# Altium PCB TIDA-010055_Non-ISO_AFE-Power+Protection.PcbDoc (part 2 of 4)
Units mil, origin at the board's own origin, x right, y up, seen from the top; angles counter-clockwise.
Board outline 3622.05 x 4330.71 mil, 4 copper layers (Top Layer, GND Layer, PWR Layer, Bottom Layer), stack 63.6 mil thick; 398 components, 177 nets, 1104 pads, 428 vias.
Unrouted connection lines stored in the file: 1.
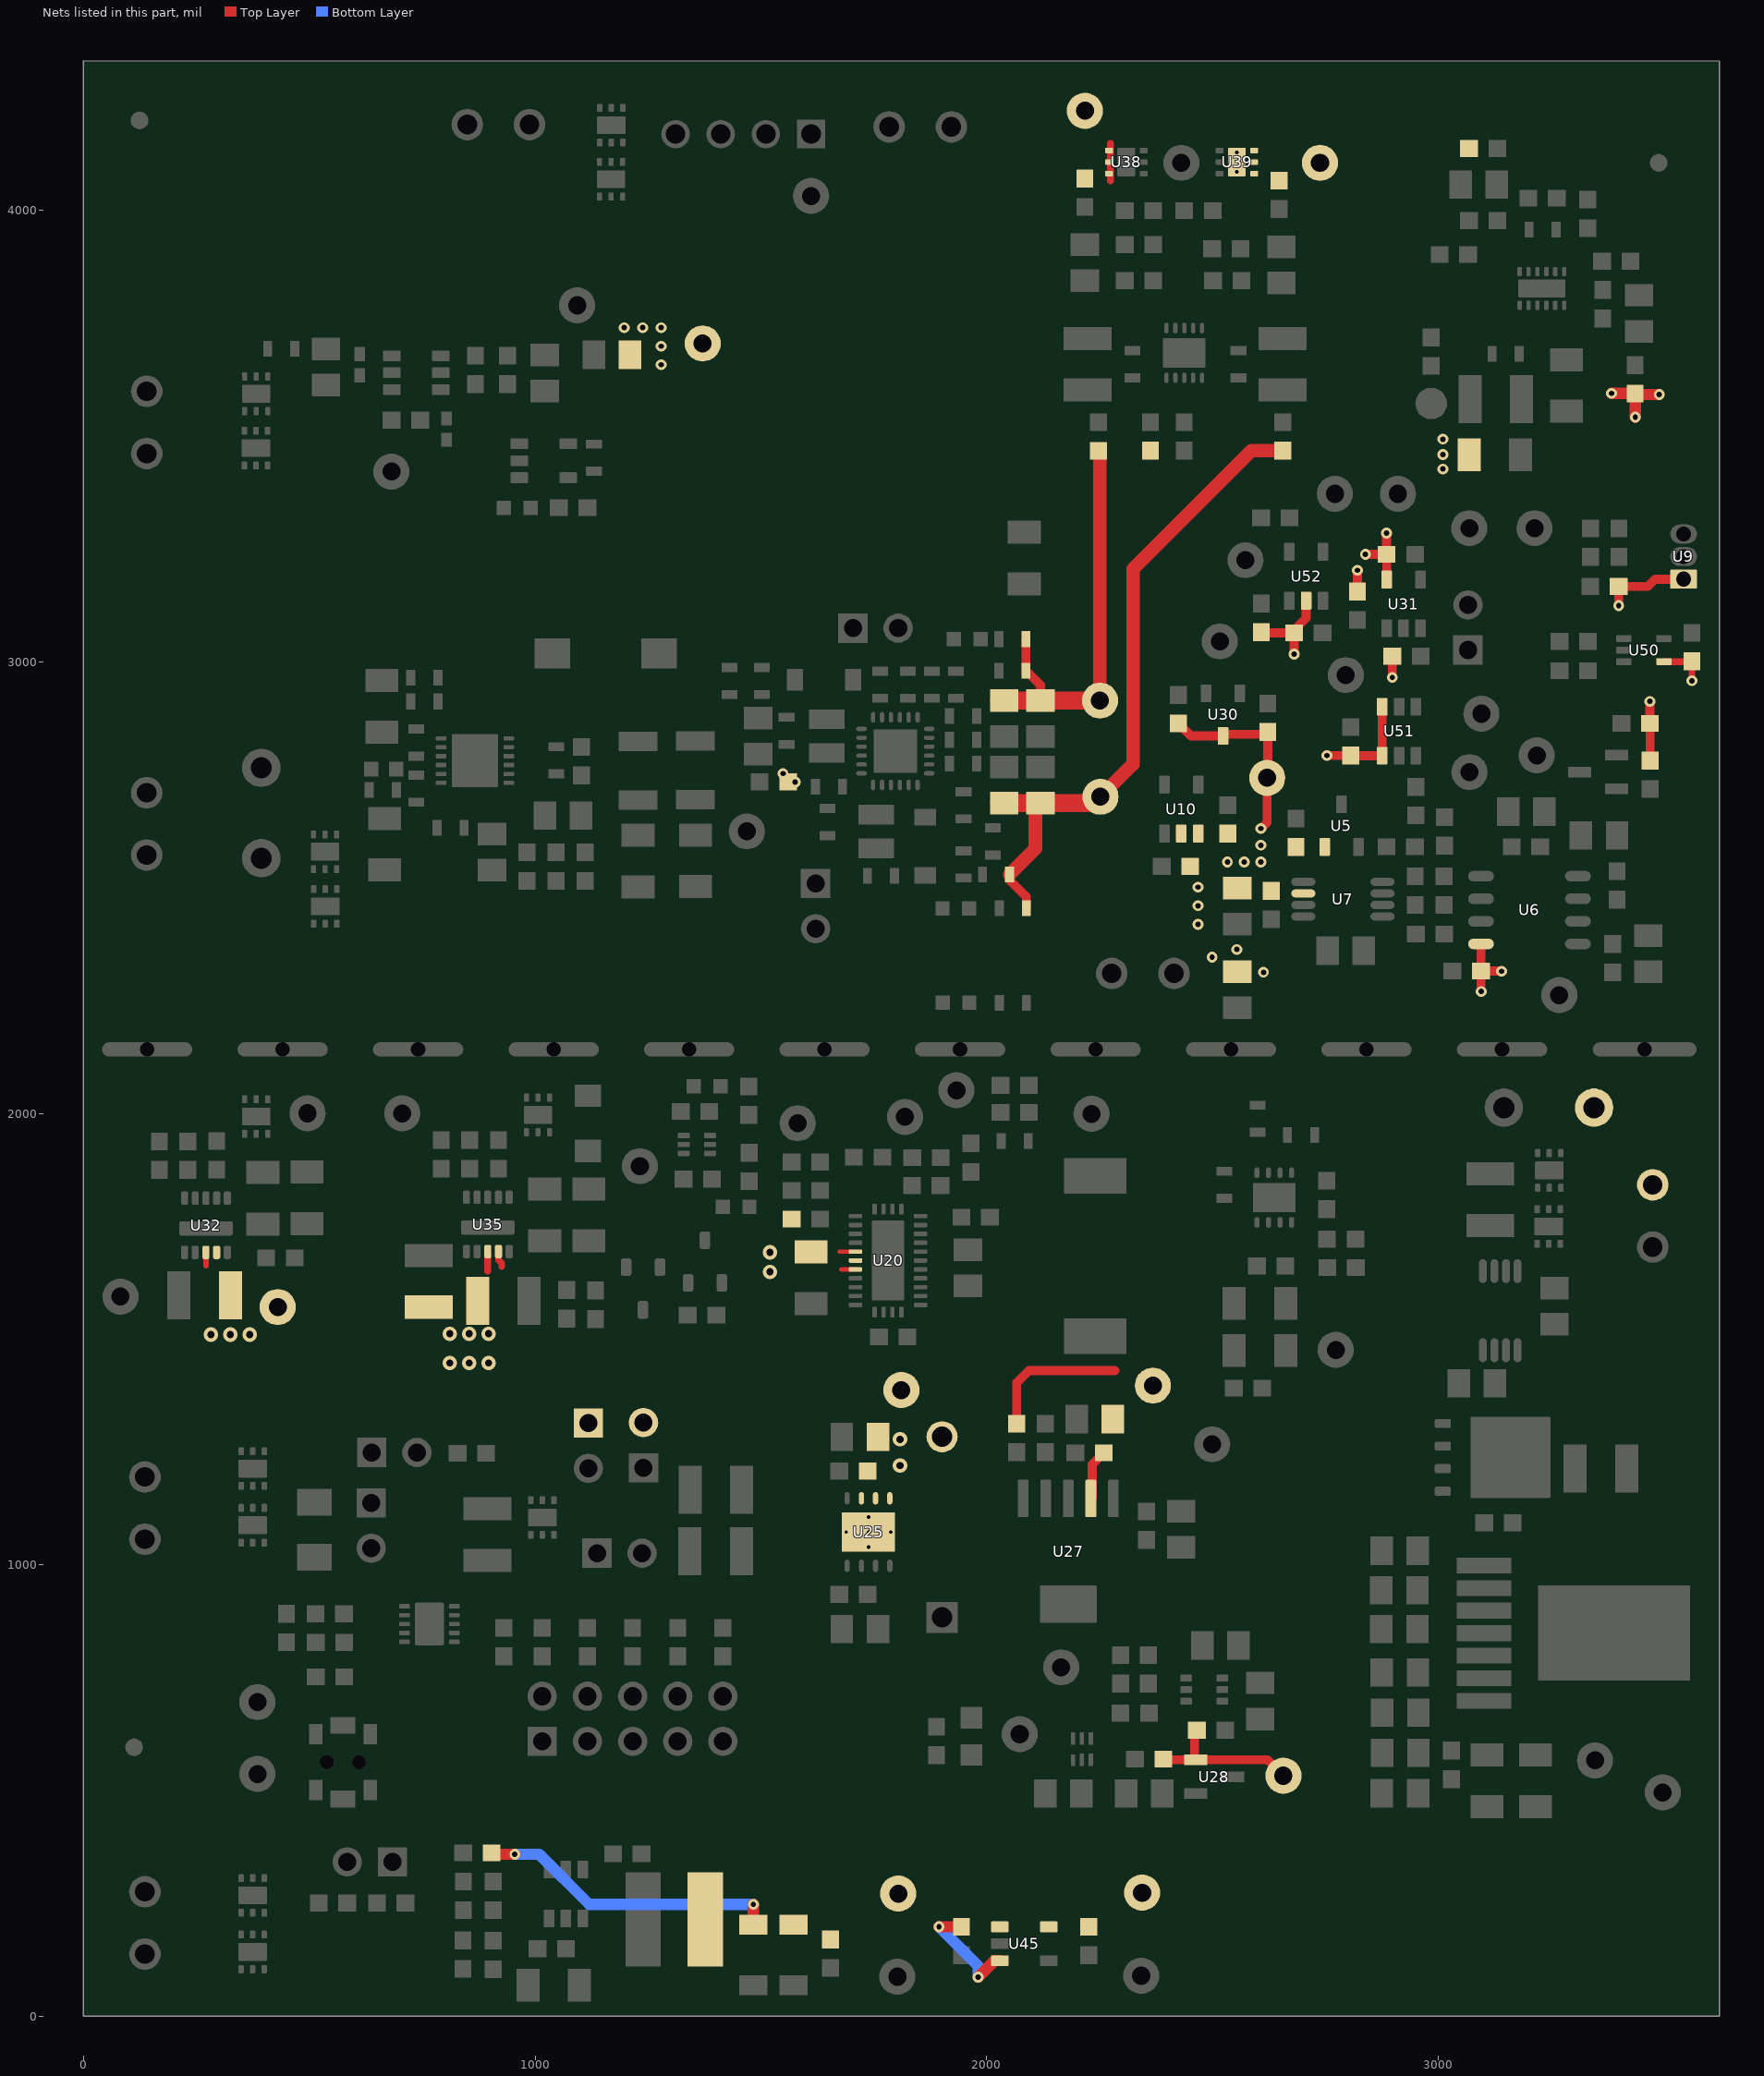
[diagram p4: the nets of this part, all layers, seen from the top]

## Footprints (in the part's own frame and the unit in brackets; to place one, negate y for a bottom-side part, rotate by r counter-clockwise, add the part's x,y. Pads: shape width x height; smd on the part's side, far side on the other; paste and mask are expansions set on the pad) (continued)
SW_PTS820 [mm] "SMT, 2-Leads, Body 3.9x2.9mm"
  rect 0.95x1.4 smd: 1(-2.075,0) 2(2.075,0)
  round 0.8 hole 0.8 unplated: MH1(0,0.9) MH2(0,-0.9)
  rect 1.15x0.75 smd: MP1(-1.575,1.525) MP2(1.575,1.525) MP3(1.575,-1.525) MP4(-1.575,-1.525)
  silkscreen extent -2.45,-2.2 2.45,2.2, body extent -2.25,-1.45 2.25,1.45, height 2
WE-PD-S [mm]
  rect 2x1.7 smd: 1(-3,0) 2(3,0)
  silkscreen extent -4.3,-4 4.3,4, body extent -3.8,-3.82 3.8,3.77, height 3.5
WE-PD_1050 [mm] "WERTH"
  rect 2x3.5 smd: 1(-4.5,0) 2(4.5,0)
  silkscreen extent -5,-5 5,5, body extent -5,-5 5,5, height 4.75
WE-SPC_4838 [mm] "WURTH"
  rect 2x5.3 smd: 1(-1.75,0) 2(1.75,0)
  silkscreen extent -0.48,-2.65 0.48,2.65, body extent -2.55,-2.55 2.55,2.55, height 4.1
WE_LQS_252012 [mm] "SMD, 2-Leads, Body 2.5x2mm, Pitch 1.9mm"
  rect 1.1x2 smd: 1(-0.95,0) 2(0.95,0)
  silkscreen extent -0.1,-1 0.1,1, body extent -1.25,-1 1.25,1, height 1.2
WEEE_Minimum [mil] "WEEElie bin"
  silkscreen extent -95,-172 99,104
Wurth_61300411021 [mm] "Header, 2.54 mm, 4x1, R/A, TH"
  rect 1.6x1.6 hole 1.1: 1(-3.81,0)
  round 1.6 hole 1.1: 2(-1.27,0) 3(1.27,0) 4(3.81,0)
  silkscreen extent -5.5,-4.04 5.08,-1.5, body extent -5.08,-10.04 5.08,0.32, height 2.55

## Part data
C1: "CAP, CERM, 4700 pF, 100 V, +/- 10%, X7R, 0603", Cap_Case=0603, Manufacturer=AVX, Supplier Part Number 1=478-1203-1-ND, TempCo=X7R, Tolerance_%=10, Value1="0.136 ohm", Value2=100V, ValueDisplayed=4700pF
C2: library part C0603C103J5RACTU, "CAP, CERM, 0.01 µF, 50 V, +/- 5%, X7R, 0603", Cap_Case=0603, Manufacturer="TDK Corporation", Supplier Part Number 1=445-5662-1-ND, TempCo=X7R, Tolerance_%=5, Value1=Unknown, Value2=50V, ValueDisplayed=0.01µF
C3 C4 C123: "CAP, CERM, 2.2 µF, 50 V,+/- 10%, X7R, 1206", Cap_Case=1206, Manufacturer="Taiyo Yuden", Supplier Part Number 1=587-2911-1-ND, TempCo=X7R, Tolerance_%=10, Value2=50V, ValueDisplayed=2.2µF
C5 C19 C23 C28 C29 C84: library part C1608X7R1H104K, "CAP, CERM, 0.12µF ±10% 50V Ceramic Capacitor X7R 0603", Cap_Case=0603, Manufacturer=KEMET, Supplier Part Number 1=399-13273-1-ND, TempCo=X7R, Tolerance_%=10, Value1="0.017 ohm", Value2=50V, ValueDisplayed=0.1µF
C6 C7: "CAP, CERM, 100 µF, 10 V, +/- 20%, X5R, 1210", Cap_Case=1210, Manufacturer=KEMET, Supplier Part Number 1=399-11631-1-ND, TempCo=X5R, Tolerance_%=20, Value1=Unknown, Value2=10V, ValueDisplayed=100µF
C8 C11: "CAP, CERM, 0.1 µF, 100 V, +/- 10%, X7R, 0805", Cap_Case=0805, Manufacturer=Kemet, Supplier Part Number 1=399-3486-1-ND, TempCo=X7R, Tolerance_%=10, Value1="0.064 ohm", Value2=100V, ValueDisplayed=0.1µF
C9 C32 C43: library part GMK325AB7106MM-T, "CAP, CERM, 10µF ±10% 35V Ceramic Capacitor X7R 1210", Cap_Case=1210, Manufacturer="Taiyo Yuden", PartNumber=GMJ325KB7106KMHP, Supplier Part Number 1=587-4890-1-ND, TempCo=X7R, Tolerance_%=20, Value1=Unknown, Value2=35V, ValueDisplayed=10µF
C10: "CAP, CERM, 1000 pF, 16 V, +/- 10%, X7R, 0603", Cap_Case=0603, Manufacturer="Wurth Elektronik", Supplier Part Number 1=732-7953-1-ND, TempCo=X7R, Tolerance_%=10, Value1=Unknown, Value2=16V, ValueDisplayed=1000pF
C16 C17 C25 C26: "CAP, CERM, 10 µF, 25 V, +/- 10%, X7S, 0805", Cap_Case=0805, Manufacturer=MuRata, Supplier Part Number 1=490-10496-1-ND, TempCo=X7S, Tolerance_%=10, Value1=Unknown, Value2=25V, ValueDisplayed=10µF
C18 C27 C33 C35 C38 C44 C63 C64 C71 C98: library part GRM188R71E105KA12D, "CAP, CERM, 1 µF, 25 V, +/- 10%, X7R, 0603", Cap_Case=0603, Manufacturer="TDK Corporation", Supplier Part Number 1=445-6931-1-ND, TempCo=X7R, Tolerance_%=10, Value1=Unknown, Value2=25V, ValueDisplayed=1µF
C20: "CAP, CERM, 6.8 pF, 50 V, +/- 4%, C0G/NP0, 0603", Cap_Case=0603, Manufacturer=AVX, Supplier Part Number 1=478-1161-1-ND, TempCo=C0G/NP0, Tolerance_%=4, Value1="0.505 ohm", Value2=50V, ValueDisplayed=6.8pF
C21: library part GRM188R71C224KA01D, "CAP, CERM, 0.22 µF, 16 V, +/- 10%, X7R, 0603", Cap_Case=0603, Manufacturer="Taiyo Yuden", Supplier Part Number 1=587-1249-1-ND, TempCo=X7R, Tolerance_%=10, Value1=Unknown, Value2=16V, ValueDisplayed=0.22µF
C22: "CAP, CERM, 10 µF, 25 V,+/- 10%, X7S, 0805", Cap_Case=0805, Manufacturer=MuRata, Supplier Part Number 1=490-10496-1-ND, TempCo=X7S, Tolerance_%=10, Value2=25V, ValueDisplayed=10µF
C24: library part 06035A5R6CAT2A, "CAP, CERM, 5.6 pF, 50 V, +/- 5%, C0G/NP0, 0603", Cap_Case=0603, Manufacturer=KEMET, Supplier Part Number 1=399-9112-1-ND, TempCo=C0G/NP0, Tolerance_%=5, Value1="0.568 ohm", Value2=50V, ValueDisplayed=5.6pF
C30: "CAP, CERM, 4700 pF, 50 V, +/- 10%, X7R, 0603", Cap_Case=0603, Manufacturer="Wurth Elektronik", Supplier Part Number 1=732-8005-1-ND, TempCo=X7R, Tolerance_%=10, Value1=Unknown, Value2=50V, ValueDisplayed=4700pF
C31: "CAP, CERM, 0.01 µF, 16 V, +/- 10%, X7R, 0603", Cap_Case=0603, Manufacturer="Wurth Elektronik", Supplier Part Number 1=732-7959-1-ND, TempCo=X7R, Tolerance_%=10, Value1=Unknown, Value2=16V, ValueDisplayed=0.01µF
C34 C37 C39 C41: "CAP, CERM, 2.2uF, 10V, +/-10%, X7R, 0805", Cap_Case=0805, Manufacturer=Kemet, Supplier Part Number 1=399-3522-1-ND, TempCo=X7R, Tolerance_%=10, Value1="0.008 ohm", Value2=10V, ValueDisplayed=2.2µF
C36 C40 C42: "CAP, CERM, 0.01 µF, 16 V,+/- 10%, X7R, 0603", Cap_Case=0603, Manufacturer="Wurth Elektronik", Supplier Part Number 1=732-7959-1-ND, TempCo=X7R, Tolerance_%=10, Value2=16V, ValueDisplayed=0.01µF
C45: library part C3216X7R1E475M, "CAP, CERM, 4.7 µF, 25 V, +/- 20%, X7R, 1206", Cap_Case=1206, Manufacturer=TDK, Supplier Part Number 1=445-1424-1-ND, TempCo=X7R, Tolerance_%=20, Value1="0.0063 ohm", Value2=25V, ValueDisplayed=4.7µF
C46 C47 C49 C54 C56 C57 C58 C61 C99 C100 C119 C135 C136 C137 C138 C139: "CAP, CERM, 0.1 µF, 25 V,+/- 10%, X5R, 0603", Cap_Case=0603, Manufacturer=AVX, Supplier Part Number 1=478-1244-1-ND, TempCo=X5R, Tolerance_%=10, Value1="0.048 ohm", Value2=25V, ValueDisplayed=0.1µF
C48 C53: library part C0805C105K8RACTU, "CAP, CERM, 1uF, 10V, +/-10%, X7R, 0805", Cap_Case=0805, Manufacturer="Samsung Electro-Mechanics", Supplier Part Number 1=1276-1275-1-ND, TempCo=X7R, Tolerance_%=10, Value1="0.015 ohm", Value2=10V, ValueDisplayed=1µF
C50 C51 C52: library part GRM21BR71H105KA12L, "CAP, CERM, 1 µF, 50 V, +/- 10%, X7R, 0805", Cap_Case=0805, Manufacturer=MuRata, Supplier Part Number 1=445-8890-1-ND, TempCo=X7R, Tolerance_%=10, Value1=Unknown, Value2=50V, ValueDisplayed=1µF
C55: "CAP, CERM, 10uF, 16V, +/-20%, X5R, 0603", Cap_Case=0603, Manufacturer="Taiyo Yuden", Supplier Part Number 1=587-3238-1-ND, TempCo=X5R, Tolerance_%=20, Value1=Unknown, Value2=16V, ValueDisplayed=10µF
C59: library part CL10B105KQ8NNNC, "CAP, CERM, 1 µF, 6.3 V, +/- 10%, X7R, 0603", Cap_Case=0603, Manufacturer="TDK Corporation", Supplier Part Number 1=445-13246-1-ND, TempCo=X7R, Tolerance_%=10, Value1=Unknown, Value2=6.3V, ValueDisplayed=1µF
C60 C87 C88 C94 C95 C121: library part GRM21BR61E106KA73L, "CAP, CERM, 10 µF, 25 V, +/- 10%, X5R, 0805", Cap_Case=0805, Manufacturer="TDK Corporation", Supplier Part Number 1=445-14387-1-ND, TempCo=X5R, Tolerance_%=10, Value1=Unknown, Value2=25V, ValueDisplayed=10µF
C65: library part GRM31CR72A105KA01L, "CAP, CERM, 1 µF, 100 V, +/- 10%, X7R, 1206", Cap_Case=2220, Manufacturer="TDK Corporation", Supplier Part Number 1=445-4467-1-ND, TempCo=X7R, Tolerance_%=10, Value1=Unknown, Value2=100V, ValueDisplayed=1µF
C66: library part GRM32ER72A225KA35L, "CAP, CERM, 2.2 µF, 100 V, +/- 10%, X7R, 1210", Cap_Case=1210, Manufacturer="TDK Corporation", Supplier Part Number 1=445-4497-1-ND, TempCo=X7R, Tolerance_%=10, Value1="0.007 ohm", Value2=100V, ValueDisplayed=2.2µF
C67: library part GRM188R71C223KA01D, "CAP, CERM, 0.022 µF, 16 V,+/- 10%, X7R, 0603", Cap_Case=0603, Manufacturer=KEMET, Supplier Part Number 1=399-1093-1-ND, TempCo=X7R, Tolerance_%=10, Value2=16V, ValueDisplayed=0.022µF
C68 C69 C78 C101 C104 C105 C133: library part GRM32ER71J106KA12L, "CAP, CERM, 10µF ±20% 50V Ceramic Capacitor X7R 1210", Cap_Case=1210, Manufacturer="Taiyo Yuden", Supplier Part Number 1=445-4537-1-ND, TempCo=X7R, Tolerance_%=10, Value1=Unknown, Value2=63V, ValueDisplayed=10µF
C70 C124 C127 C131: library part GRM188R71H104KA93D, "CAP, CERM, 0.12µF ±10% 50V Ceramic Capacitor X7R 0603", Cap_Case=0603, Manufacturer=KEMET, Supplier Part Number 1=399-13273-1-ND, TempCo=X7R, Tolerance_%=10, Value2=50V, ValueDisplayed=0.1µF
C72 C76: "CAP, CERM, 10 µF, 16 V,+/- 20%, X5R, 0603", Cap_Case=0603, Manufacturer="Taiyo Yuden", Supplier Part Number 1=587-3238-1-ND, TempCo=X5R, Tolerance_%=20, Value2=16V, ValueDisplayed=10µF
C73 C77: "CAP, CERM, 0.022 µF, 100 V,+/- 5%, X7R, 0805", Cap_Case=0805, Manufacturer=AVX, Supplier Part Number 1=478-3747-1-ND, TempCo=X7R, Tolerance_%=5, Value1="0.052 ohm", Value2=100V, ValueDisplayed=0.022µF
C74: library part C1005X5R1A225K050BC, "CAP CER 2.2UF 100V X7S 1206", Cap_Case=0402, Manufacturer="TDK Corporation", Supplier Part Number 1=445-5207-1-ND, TempCo=X7S, Tolerance_%=10, Value2=100V, ValueDisplayed=2.2µF
C75: library part C2012X7R1H474K125AB, "CAP, CERM, 0.47 µF, 50 V,+/- 10%, X7R, 0805", Cap_Case=0805, Manufacturer="Murata Electronics North America", Supplier Part Number 1=490-4788-1-ND, TempCo=X7R, Tolerance_%=10, Value1="0.022012 ohm", Value2=50V, ValueDisplayed=0.47µF
C79 C80 C83 C125 C126: library part UMK107AB7105KA-T, "CAP, CERM,  1UF 50V X5R 0603", Cap_Case=0603, Manufacturer="Taiyo Yuden", Supplier Part Number 1=587-2400-1-ND, TempCo=X7R, Tolerance_%=10, Value2=50V, ValueDisplayed=1µF
C81 C102 C103 C106 C107: library part C3216X5R1C476M160AB, "CAP, CERM,47µF ±20% 16V Ceramic Capacitor JB 1206", Cap_Case=1206, Manufacturer="Taiyo Yuden", Supplier Part Number 1=587-5425-1-ND, TempCo=X5R, Tolerance_%=15, Value2=16V, ValueDisplayed=47µF
C82: "CAP, CERM, 2200 pF, 50 V,+/- 5%, C0G/NP0, 0603", Cap_Case=0603, Manufacturer=MuRata, Supplier Part Number 1=490-1459-1-ND, TempCo=C0G/NP0, Tolerance_%=5, Value2=50V, ValueDisplayed=2200pF
C85 C86 C92 C93: library part 06035A101JAT2A, "CAP, CERM, 100 pF, 50 V, +/- 5%, C0G/NP0, 0603", Cap_Case=0603, Manufacturer=AVX, Supplier Part Number 1=478-6022-1-ND, TempCo=C0G/NP0, Tolerance_%=5, Value1="0.119 ohm", Value2=50V, ValueDisplayed=100pF
C89 C90 C96 C97: "CAP, CERM, 0.1 uF, 100 V, +/- 10%, X7R, 0805", Cap_Case=0805, Manufacturer=TDK, PartNumber=C2012X7R2A104K125AA, Supplier Part Number 1=445-1418-1-ND, TempCo=X7R, Tolerance_%=10%, Value1="0.020726 ohm", Value2=100V, ValueDisplayed=0.1uF
C91: library part CMP-0006814-2, "CAP, CERM, 0.01 uF, 10 V, +/- 10%, X7R, 0603", Cap_Case=0603, Manufacturer=AVX, Supplier Part Number 1=478-7938-2-ND, TempCo=X7R, Tolerance_%=10%, Value1=Unknown, Value2=10V, ValueDisplayed=0.01uF
C118: "CAP, CERM, 0.22 µF, 16 V, +/- 10%, X7R, 0805", Cap_Case=0805, Manufacturer=AVX, Supplier Part Number 1=478-1400-1-ND, TempCo=X7R, Tolerance_%=10, Value1="0.016 ohm", Value2=16V, ValueDisplayed=0.22µF
C120 C122: "CAP, CERM, 1000 pF, 50 V,+/- 5%, C0G/NP0, AEC-Q200 Grade 1, 0402", Cap_Case=0402, Manufacturer=TDK, Supplier Part Number 1=445-6885-1-ND, TempCo=C0G/NP0, Tolerance_%=5, Value2=50V, ValueDisplayed=1000pF
C128 C132: "CAP, CERM, 22 pF, 50 V,+/- 5%, C0G/NP0, 0603", Cap_Case=0603, Manufacturer=AVX, Supplier Part Number 1=478-1167-1-ND, TempCo=C0G/NP0, Tolerance_%=5, Value1="0.259 ohm", Value2=50V, ValueDisplayed=22pF
C129 C130: library part GRM31CR71A226KE15L, "CAP, CERM, 22 µF, 10 V,+/- 10%, X7R, 1206", Cap_Case=1206, Manufacturer="Samsung Electro-Mechanics", Supplier Part Number 1=1276-3148-1-ND, TempCo=X7R, Tolerance_%=10, Value2=10V, ValueDisplayed=22µF
C134: library part C3216X5R1C476M160AB, "CAP, CERM, 47 µF, 16 V,+/- 15%, X5R, 1206", Cap_Case=1206, Manufacturer="Taiyo Yuden", Supplier Part Number 1=587-5425-1-ND, TempCo=X5R, Tolerance_%=15, Value2=16V, ValueDisplayed=47µF
D1 D6 D10 D11 D14 D15: "LED, Green, SMD", Color=green, Manufacturer=Lite-On, Supplier Part Number 1=160-1435-1-ND, Value1=W, Value2=2V
D4: "Diode Schottky 40V 1.1A Surface Mount DO-219AB (SMF)", Manufacturer=Vishay, PartNumber=SL04-HE3-08, Supplier Part Number 1=SL04-HE3-08CT-ND
D7 D8: "Diode, Schottky, 45 V, 2 A, AEC-Q101, SOD-123FL", Manufacturer="ON Semiconductor", Supplier Part Number 1=NTS245SFT1GOSCT-ND, Value1=2A, Value2=0.63V
D12: library part 1N4002-T, "Diode Standard 50V 1A Through Hole DO-41", Manufacturer="ON Semiconductor", Supplier Part Number 1=1N4001RLGOSCT-ND, Value1=1A, Value2=1V
D13: "LED, Red, SMD", Color=red, Manufacturer=Lite-On, PartNumber=LTST-C170KRKT, Supplier Part Number 1=160-1415-1-ND, Value1=W, Value2=2V
FID1 FID2 FID3: "Fiducial mark.  There is nothing to buy or mount.", Manufacturer=N/A
H1 H2 H3 H4 H5 H6 H7 H8 H9 H10: "Bumpon, Cylindrical, 0.312 X 0.200, Black", Manufacturer=3M, Supplier Part Number 1=SJ5746-0-ND
J1 J4 J6 J11 J14 J19 J20 J21: "Conn Term Block, 2POS, 3.5mm, TH", Manufacturer="Phoenix Contact", Supplier Part Number 1=277-5719-ND
J3: "Header, 2.54 mm, 4x1, Gold, R/A, TH", Color=Black, Manufacturer="Wurth Elektronik", Supplier Part Number 1=732-5337-ND
J7 J8 J9 J12 J15 J16 J17 J18: "Header, 100mil, 2x1, Gold, TH", Color=Black, Current_A=3, Manufacturer="Sullins Connector Solutions", Supplier Part Number 1=S1011E-02-ND, Voltage_V=1800
J10: "Header, 100mil, 2x1, Gold, TH", Manufacturer="Sullins Connector Solutions", Supplier Part Number 1=S1011E-02-ND
J13: "Header, 100mil, 5x2, Tin, TH", Color=Black, Current_A=3, Manufacturer="Sullins Connector Solutions", Supplier Part Number 1=S2012E-05-ND, Voltage_V=1800
L1: library part LQM18PN2R2MFH, "2.2µH Shielded Multilayer Inductor 500mA 250mOhm 0603 (1608 Metric)", Manufacturer="TDK Corporation", PartNumber=MLZ1608A2R2WT000, Supplier Part Number 1=445-6385-1-ND, Value1="0.38 ohm", Value2=0.35A, ValueDisplayed=2.2µH
L2: "Inductor, Shielded Drum Core, Ferrite, 47 µH, 0.85 A, 0.315 ohm, SMD", Manufacturer="Wurth Elektronik", Supplier Part Number 1=732-1183-1-ND, Value1="0.315 ohm", Value2=0.85A, ValueDisplayed=47µH
L3: "Ferrite Bead, 600 ohm @ 100 MHz, 1.3 A, 0603", Manufacturer=MuRata, Supplier Part Number 1=490-5258-1-ND, Value1="0.15 ohm", Value2=1.3A
L4 L5: "Inductor, Wirewound, Ferrite, 10 µH, 0.47 A, 0.435 ohm, SMD", Manufacturer="Wurth Elektronik", Supplier Part Number 1=732-5428-1-ND, Value1="0.435 ohm", Value2=0.47A, ValueDisplayed=10µH
L7: "Inductor, Shielded Drum Core, Ferrite, 22 µH, 3 A, 0.042 ohm, SMD", Manufacturer="Wurth Elektronik", Supplier Part Number 1=732-2992-1-ND, Value1="0.042 ohm", Value2=3A, ValueDisplayed=22µH
L8: library part CMP-0064461-2, "Inductor, Shielded Drum Core, Ferrite, 15 uH, 1.4 A, 0.118 ohm, SMD", Manufacturer="Wurth Elektronik", Supplier Part Number 1=732-3038-1-ND, Value1="0.118 ohm", Value2=1.4A, ValueDisplayed=15uH
Logo1: library part CMP-0074769-1
Logo2: library part Pb-Free
Logo3: library part FCC_disclaimer, "FCC_disclaimer"
Logo4: library part ESD_Susceptible, "ESD Susceptible Symbol"
PT1 PT2: library part POLYSWITCH_RXE135, "PTC THERMISTOR C 830-A 160-A 70", Manufacturer=Raychem, Supplier Part Number 1=495-76377-ND
Q1: library part CMP-0000810-1, "MOSFET, N-CH, 60 V, 100 A, DQJ0008A (VSONP-8)", Alternate Manufacturer=None, Manufacturer="Texas Instruments", Supplier Part Number 1=296-30573-1-ND, Value1=0.005, Value2="36 nC"
Q2 Q3: library part CMP-0000768-1, "MOSFET, N-CH, 60 V, 115 A, SOT-23", Alternate Manufacturer=None, Manufacturer="Fairchild Semiconductor", Supplier Part Number 1=2N7002NCT-ND
R1: "RES, 1.21 k, 1%, 0.1 W, 0603", Manufacturer=Vishay-Dale, Power_W=0.1, Supplier Part Number 1=541-1.21KHCT-ND, TempCo="100 ppm/C", Tolerance_%=1, Value1=1%, Value2=0.1W, Value_Code=1k21, ValueDisplayed=1.21k
R2 R22 R23 R52: "RES, 1.00, 1%, 0.1 W, 0603", Manufacturer=Vishay-Dale, Power_W=0.1, Supplier Part Number 1=541-3956-1-ND, TempCo="100 ppm/C", Tolerance_%=1, Value1=1%, Value2=0.1W, Value_Code=1R00, ValueDisplayed=1.00
R3: "RES, 113 k, 1%, 0.1 W, 0603", Manufacturer=Vishay-Dale, Power_W=0.1, Supplier Part Number 1=541-113KHCT-ND, TempCo="100 ppm/C", Tolerance_%=1, Value1=1%, Value2=0.1W, Value_Code=113k
R4: "RES, 16.9 k, 1%, 0.1 W, 0603", Manufacturer=Vishay-Dale, Power_W=0.1, Supplier Part Number 1=541-16.9KHCT-ND, TempCo="100 ppm/C", Tolerance_%=1, Value1=1%, Value2=0.1W, Value_Code=16k9, ValueDisplayed=16.9k
R5: library part CRCW0603100KFKEA, "RES, 100 k, 1%, 0.1 W, 0603", Manufacturer="Yageo America", Power_W=0.1, Supplier Part Number 1=YAG2319CT-ND, TempCo="100 ppm/C", Tolerance_%=1, Value1=1%, Value2=0.1W, Value_Code=100k
R6 R101 R102: "RES, 100 k, 1%, 0.1 W, 0603", Manufacturer="Yageo America", Power_W=0.1, Supplier Part Number 1=311-100KHRCT-ND, TempCo="200 ppm/C", Tolerance_%=1, Value1=1%, Value2=0.1W, Value_Code=100k
R7: "RES, 3.00 k, 1%, 0.1 W, 0603", Manufacturer="Yageo America", Power_W=0.1, Supplier Part Number 1=311-3.00KHRCT-ND, TempCo="200 ppm/C", Tolerance_%=1, Value1=1%, Value2=0.1W, Value_Code=3k00, ValueDisplayed=3.00k
R8 R9: library part CRCW12061R00FKEA, "RES, 1.00, 1%, 0.25 W, 1206", Manufacturer="Yageo America", Power_W=0.25, Supplier Part Number 1=311-1.00FRCT-ND, TempCo="100 ppm/C", Tolerance_%=1, Value1=1%, Value2=0.25W, Value_Code=1R00, ValueDisplayed=1.00
R10: "RES, 2.00 k, 1%, 0.1 W, 0603", Manufacturer=Vishay-Dale, Power_W=0.1, Supplier Part Number 1=541-2.00KHCT-ND, TempCo="100 ppm/C", Tolerance_%=1, Value1=1%, Value2=0.1W, Value_Code=2k00, ValueDisplayed=2.00k
R11: "RES, 1.96 k, 1%, 0.1 W, 0603", Manufacturer="Yageo America", Power_W=0.1, Supplier Part Number 1=311-1.96KHRCT-ND, TempCo="200 ppm/C", Tolerance_%=1, Value1=1%, Value2=0.1W, Value_Code=1k96, ValueDisplayed=1.96k
R14 R21: "RES, 5.36 k, 1%, 0.1 W, 0603", Manufacturer=Vishay-Dale, Power_W=0.1, Supplier Part Number 1=541-5.36KHCT-ND, TempCo="100 ppm/C", Tolerance_%=1, Value1=1%, Value2=0.1W, Value_Code=5k36, ValueDisplayed=5.36k
R15: "RES, 976 k, 1%, 0.1 W, 0603", Manufacturer=Vishay-Dale, Power_W=0.1, Supplier Part Number 1=541-976KHCT-ND, TempCo="100 ppm/C", Tolerance_%=1, Value1=1%, Value2=0.1W, Value_Code=976k
R16: "RES, 86.6 k, 1%, 0.1 W, 0603", Manufacturer=Vishay-Dale, Power_W=0.1, Supplier Part Number 1=541-86.6KHCT-ND, TempCo="100 ppm/C", Tolerance_%=1, Value1=1%, Value2=0.1W, Value_Code=86k6, ValueDisplayed=86.6k
R17: "RES, 105 k, 1%, 0.1 W, 0603", Manufacturer=Vishay-Dale, Power_W=0.1, Supplier Part Number 1=541-105KHCT-ND, TempCo="100 ppm/C", Tolerance_%=1, Value1=1%, Value2=0.1W, Value_Code=105k
R18: "RES, 1.30 M, 1%, 0.1 W, 0603", Manufacturer=Vishay-Dale, Power_W=0.1, Supplier Part Number 1=541-1.30MHCT-ND, TempCo="100 ppm/C", Tolerance_%=1, Value1=1%, Value2=0.1W, Value_Code=1M30, ValueDisplayed=1.30M
R19: "RES, 0, 5%, 0.25 W, 1206", Manufacturer=Vishay-Dale, Power_W=0.25, Supplier Part Number 1=541-0.0ECT-ND, TempCo="200 ppm/C", Tolerance_%=5, Value1=5%, Value2=0.25W, Value_Code=0000, ValueDisplayed=0
R20 R44 R45 R47 R50 R117: "RES, 100, 1%, 0.1 W, 0603", Manufacturer=Vishay-Dale, Power_W=0.1, Supplier Part Number 1=541-100HCT-ND, TempCo="100 ppm/C", Tolerance_%=1, Value1=1%, Value2=0.1W, Value_Code=100R, ValueDisplayed=100
R24 R25 R26 R31 R33 R36 R38 R40 R41 R96: "RES, 0, 5%, 0.1 W, 0603", Manufacturer=Vishay-Dale, Power_W=0.1, Supplier Part Number 1=541-0.0GCT-ND, TempCo="200 ppm/C", Tolerance_%=5, Value1=5%, Value2=0.1W, Value_Code=0000, ValueDisplayed=0
R27 R28 R30 R34: "RES, 249 k, 1%, 0.1 W, 0603", Manufacturer=Vishay-Dale, Power_W=0.1, Supplier Part Number 1=541-249KHCT-ND, TempCo="100 ppm/C", Tolerance_%=1, Value1=1%, Value2=0.1W, Value_Code=249k
R29: library part RNCF0603TKY10K0, "RES, 10.0k ohm, 1%, 0.1W, 0603", Manufacturer="Stackpole Electronics Inc", Power_W=0.063, Supplier Part Number 1=541-10.0KHCT-ND, TempCo="5 ppm/C", Tolerance_%=0.01, Value1=0.01%, Value2=0.063W, Value_Code=10k0
R32 R37: "RES, 75.0 k, 1%, 0.1 W, 0603", Manufacturer=Vishay-Dale, Power_W=0.1, Supplier Part Number 1=541-75.0KHCT-ND, TempCo="100 ppm/C", Tolerance_%=1, Value1=1%, Value2=0.1W, Value_Code=75k0, ValueDisplayed=75.0k
R35: "RES, 27.0 k, 1%, 0.1 W, 0603", Manufacturer="Yageo America", Power_W=0.1, Supplier Part Number 1=311-27.0KHRCT-ND, TempCo="200 ppm/C", Tolerance_%=1, Value1=1%, Value2=0.1W, Value_Code=27k0, ValueDisplayed=27.0k
R39: "RES, 24.0 k, 1%, 0.1 W, 0603", Manufacturer="Yageo America", Power_W=0.1, Supplier Part Number 1=311-24.0KHRCT-ND, TempCo="200 ppm/C", Tolerance_%=1, Value1=1%, Value2=0.1W, Value_Code=24k0, ValueDisplayed=24.0k
R42 R43 R48 R49 R118: "RES, 0 ohm, 5%, 0.1W, 0603", Manufacturer=Vishay-Dale, Power_W=0.1, Supplier Part Number 1=541-0.0GCT-ND, TempCo="200 ppm/C", Tolerance_%=5, Value1=5%, Value2=0.1W, Value_Code=0000
R46: "RES, 2.55 k, 1%, 0.1 W, 0603", Manufacturer=Vishay-Dale, Power_W=0.1, Supplier Part Number 1=541-2.55KHCT-ND, TempCo="100 ppm/C", Tolerance_%=1, Value1=1%, Value2=0.1W, Value_Code=2k55, ValueDisplayed=2.55k
R51: "RES, 0, 5%, 0.25 W, 1206", Manufacturer="Yageo America", Power_W=0.25, Supplier Part Number 1=311-0.0ERCT-ND, TempCo="200 ppm/C", Tolerance_%=5, Value1=5%, Value2=0.25W, Value_Code=0000, ValueDisplayed=0
R53: "RES, 49.9 k, 1%, 0.1 W, 0603", Manufacturer=Vishay-Dale, Power_W=0.1, Supplier Part Number 1=541-49.9KHCT-ND, TempCo="100 ppm/C", Tolerance_%=1, Value1=1%, Value2=0.1W, Value_Code=49k9, ValueDisplayed=49.9k
R54: "RES, 887 k, 1%, 0.1 W, 0603", Manufacturer=Vishay-Dale, Power_W=0.1, Supplier Part Number 1=541-887KHCT-ND, TempCo="100 ppm/C", Tolerance_%=1, Value1=1%, Value2=0.1W, Value_Code=887k
R55 R68: "RES, 10.0 k, 1%, 0.1 W, 0603", Manufacturer=Vishay-Dale, Power_W=0.1, Supplier Part Number 1=541-10.0KHCT-ND, TempCo="100 ppm/C", Tolerance_%=1, Value1=1%, Value2=0.1W, Value_Code=10k0, ValueDisplayed=10.0k
R56: "RES, 29.4 k, 1%, 0.1 W, 0603", Manufacturer=Vishay-Dale, Power_W=0.1, Supplier Part Number 1=541-29.4KHCT-ND, TempCo="100 ppm/C", Tolerance_%=1, Value1=1%, Value2=0.1W, Value_Code=29k4, ValueDisplayed=29.4k
R57: "RES, 300, 1%, 0.1 W, 0603", Manufacturer="Yageo America", Power_W=0.1, Supplier Part Number 1=311-300HRCT-ND, TempCo="200 ppm/C", Tolerance_%=1, Value1=1%, Value2=0.1W, Value_Code=300R, ValueDisplayed=300
R58: "RES, 34.0 k, 1%, 0.1 W, 0603", Manufacturer=Vishay-Dale, Power_W=0.1, Supplier Part Number 1=541-34.0KHCT-ND, TempCo="100 ppm/C", Tolerance_%=1, Value1=1%, Value2=0.1W, Value_Code=34k0, ValueDisplayed=34.0k
R59: "RES, 7.50 k, 1%, 0.1 W, 0603", Manufacturer=Vishay-Dale, Power_W=0.1, Supplier Part Number 1=541-7.50KHCT-ND, TempCo="100 ppm/C", Tolerance_%=1, Value1=1%, Value2=0.1W, Value_Code=7k50, ValueDisplayed=7.50k
R60: "RES, 13.3 k, 1%, 0.1 W, 0603", Manufacturer=Vishay-Dale, Power_W=0.1, Supplier Part Number 1=541-13.3KHCT-ND, TempCo="100 ppm/C", Tolerance_%=1, Value1=1%, Value2=0.1W, Value_Code=13k3, ValueDisplayed=13.3k
R61: "RES, 26.7 k, 1%, 0.1 W, 0603", Manufacturer=Vishay-Dale, Power_W=0.1, Supplier Part Number 1=541-26.7KHCT-ND, TempCo="100 ppm/C", Tolerance_%=1, Value1=1%, Value2=0.1W, Value_Code=26k7, ValueDisplayed=26.7k
R62: "RES, 44.2 k, 1%, 0.1 W, 0603", Manufacturer=Vishay-Dale, Power_W=0.1, Supplier Part Number 1=541-44.2KHCT-ND, TempCo="100 ppm/C", Tolerance_%=1, Value1=1%, Value2=0.1W, Value_Code=44k2, ValueDisplayed=44.2k
R63: "RES, 267 k, 1%, 0.1 W, 0603", Manufacturer=Vishay-Dale, Power_W=0.1, Supplier Part Number 1=541-267KHCT-ND, TempCo="100 ppm/C", Tolerance_%=1, Value1=1%, Value2=0.1W, Value_Code=267k
R64: "RES, 93.1 k, 1%, 0.1 W, 0603", Manufacturer="Yageo America", Power_W=0.1, Supplier Part Number 1=311-93.1KHRCT-ND, TempCo="200 ppm/C", Tolerance_%=1, Value1=1%, Value2=0.1W, Value_Code=93k1, ValueDisplayed=93.1k
R65: "RES, 68.1 k, 1%, 0.125 W, 0805", Manufacturer=Panasonic, Power_W=0.125, Supplier Part Number 1=P68.1KCCT-ND, TempCo="100 ppm/C", Tolerance_%=1, Value1=1%, Value2=0.125W, Value_Code=68k1, ValueDisplayed=68.1k
R66: "RES, 5.62 k, 0.1%, 0.125 W, 0805", Manufacturer="Yageo America", Power_W=0.125, Supplier Part Number 1=YAG4923CT-ND, TempCo="25 ppm/C", Tolerance_%=0.1, Value1=0.1%, Value2=0.125W, Value_Code=5k62, ValueDisplayed=5.62k
R67: "RES, 150 k, 1%, 0.1 W, 0603", Manufacturer="Yageo America", Power_W=0.1, Supplier Part Number 1=311-150KHRCT-ND, TempCo="200 ppm/C", Tolerance_%=1, Value1=1%, Value2=0.1W, Value_Code=150k
R69: "RES, 11.8 k, 1%, 0.125 W, 0805", Manufacturer=Panasonic, Power_W=0.125, Supplier Part Number 1=P11.8KCCT-ND, TempCo="100 ppm/C", Tolerance_%=1, Value1=1%, Value2=0.125W, Value_Code=11k8, ValueDisplayed=11.8k
R70: "RES, 1.07 k, 1%, 0.125 W, 0805", Manufacturer=Panasonic, Power_W=0.125, Supplier Part Number 1=P1.07KCCT-ND, TempCo="100 ppm/C", Tolerance_%=1, Value1=1%, Value2=0.125W, Value_Code=1k07, ValueDisplayed=1.07k
R71: "RES, 100 k, 1%, 0.2 W, 0805", Manufacturer=Vishay/Beyschlag, Power_W=0.2, Supplier Part Number 1=MCU0805-100K-CFCT-ND, TempCo="50 ppm/C", Tolerance_%=1, Value1=1%, Value2=0.2W, Value_Code=100k
R72: "RES, 39.0 k, 1%, 0.1 W, 0603", Manufacturer="Yageo America", Power_W=0.1, Supplier Part Number 1=311-39.0KHRCT-ND, TempCo="200 ppm/C", Tolerance_%=1, Value1=1%, Value2=0.1W, Value_Code=39k0, ValueDisplayed=39.0k
R73: "RES, 63.4 k, 1%, 0.1 W, 0603", Manufacturer="Yageo America", Power_W=0.1, Supplier Part Number 1=311-63.4KHRCT-ND, TempCo="200 ppm/C", Tolerance_%=1, Value1=1%, Value2=0.1W, Value_Code=63k4, ValueDisplayed=63.4k
R74: "RES, 37.4 k, 1%, 0.1 W, 0603", Manufacturer="Yageo America", Power_W=0.1, Supplier Part Number 1=311-37.4KHRCT-ND, TempCo="200 ppm/C", Tolerance_%=1, Value1=1%, Value2=0.1W, Value_Code=37k4, ValueDisplayed=37.4k
R75 R85 R99 R100: "RES, 1.00 k, 1%, 0.1 W, AEC-Q200 Grade 0, 0603", Manufacturer=Panasonic, Power_W=0.1, Supplier Part Number 1=P1.00KHCT-ND, TempCo="100 ppm/C", Tolerance_%=1, Value1=1%, Value2=0.1W, Value_Code=1k00, ValueDisplayed=1.00k
R76 R103 R104 R110 R111: "RES, 0, 5%, 0.1 W, 0603", Manufacturer=Panasonic, Power_W=0.1, Supplier Part Number 1=P0.0GCT-ND, TempCo="600 ppm/C", Tolerance_%=5, Value1=5%, Value2=0.1W, Value_Code=0000, ValueDisplayed=0
R77 R78: "RES, 0.33, 1%, 0.5 W, 1206", Manufacturer="Stackpole Electronics Inc", Power_W=0.5, Supplier Part Number 1=CSR1206FKR330CT-ND, TempCo="100 ppm/C", Tolerance_%=1, Value1=1%, Value2=0.5W, Value_Code=R330, ValueDisplayed=0.33
R79: "RES, 10.0 k, 1%, 0.1 W, 0603", Manufacturer=Vishay-Dale, PartNumber=CRCW060310K0FKEA, Power_W=100mW, Supplier Part Number 1=541-10.0KHCT-ND, TempCo="100 ppm/C", Tolerance_%=1%, Value2=0.1W, Value_Code=10k0, ValueDisplayed=10.0k
R80: "RES, 4.75 k, 1%, 0.1 W, 0603", Manufacturer=Vishay-Dale, PartNumber=CRCW06034K75FKEA, Power_W=100mW, Supplier Part Number 1=541-4.75KHCT-ND, TempCo="100 ppm/C", Tolerance_%=1%, Value2=0.1W, Value_Code=4k75, ValueDisplayed=4.75k
R81: "RES, 1.37 k, 1%, 0.1 W, 0603", Manufacturer="Yageo America", Power_W=0.1, Supplier Part Number 1=311-1.37KHRCT-ND, TempCo="200 ppm/C", Tolerance_%=1, Value1=1%, Value2=0.1W, Value_Code=1k37, ValueDisplayed=1.37k
R82: "RES, 16.5 k, 1%, 0.1 W, 0603", Manufacturer="Yageo America", Power_W=0.1, Supplier Part Number 1=311-16.5KHRCT-ND, TempCo="200 ppm/C", Tolerance_%=1, Value1=1%, Value2=0.1W, Value_Code=16k5, ValueDisplayed=16.5k
R83: library part CMP-0022004-2, "RES, 10.0, 1%, 0.25 W, 0603", Manufacturer=Vishay-Dale, Power_W=250mW, Supplier Part Number 1=541-10.0SCT-ND, TempCo="100 ppm/C", Tolerance_%=1%, Value2=0.25W, Value_Code=10R0, ValueDisplayed=10.0
R84: library part RT0603DRE076R9L, "6.98 kOhms ±0.5% 0.1W, 1/10W Chip Resistor 0603 (1608 Metric) Thin Film", Manufacturer="Yageo America", Power_W=0.1, Supplier Part Number 1=311-6.98KDCT-ND, TempCo="50 ppm/C", Tolerance_%=0.5, Value1=0.5%, Value2=0.1W, Value_Code="6.98 K"
R86 R87 R94 R119: "RES, 10.0 k, 1%, 0.1 W, 0603", Manufacturer="Yageo America", Power_W=0.1, Supplier Part Number 1=311-10.0KHRCT-ND, TempCo="200 ppm/C", Tolerance_%=1, Value1=1%, Value2=0.1W, Value_Code=10k0, ValueDisplayed=10.0k
R88 R91 R108: "RES, 102 k, 1%, 0.1 W, 0603", Manufacturer=Vishay-Dale, Power_W=0.1, Supplier Part Number 1=541-102KHCT-ND, TempCo="100 ppm/C", Tolerance_%=1, Value1=1%, Value2=0.1W, Value_Code=102k
R89 R90 R92 R93: "RES, 21.5 k, 1%, 0.1 W, 0603", Manufacturer=Vishay-Dale, Power_W=0.1, Supplier Part Number 1=541-21.5KHCT-ND, TempCo="100 ppm/C", Tolerance_%=1, Value1=1%, Value2=0.1W, Value_Code=21k5, ValueDisplayed=21.5k
R95: "RES, 0, 5%, 0.125 W, 0805", Manufacturer=Vishay-Dale, Power_W=0.125, Supplier Part Number 1=541-0.0ACT-ND, TempCo="200 ppm/C", Tolerance_%=5, Value1=5%, Value2=0.125W, Value_Code=0000, ValueDisplayed=0
R97 R98: "RES, 47.0 k, 1%, 0.1 W, 0603", Manufacturer="Yageo America", Power_W=0.1, Supplier Part Number 1=311-47.0KHRCT-ND, TempCo="200 ppm/C", Tolerance_%=1, Value1=1%, Value2=0.1W, Value_Code=47k0, ValueDisplayed=47.0k
R105: "RES, 402 k, 1%, 0.1 W, 0603", Manufacturer=Vishay-Dale, Power_W=0.1, Supplier Part Number 1=541-402KHCT-ND, TempCo="100 ppm/C", Tolerance_%=1, Value1=1%, Value2=0.1W, Value_Code=402k
R106: "RES, 49.9, 1%, 0.1 W, 0603", Manufacturer=Vishay-Dale, Power_W=0.1, Supplier Part Number 1=541-49.9HCT-ND, TempCo="100 ppm/C", Tolerance_%=1, Value1=1%, Value2=0.1W, Value_Code=49R9, ValueDisplayed=49.9
R107: "RES, 133 k, 1%, 0.1 W, 0603", Manufacturer=Vishay-Dale, Power_W=0.1, Supplier Part Number 1=541-133KHCT-ND, TempCo="100 ppm/C", Tolerance_%=1, Value1=1%, Value2=0.1W, Value_Code=133k
R109: "RES, 25.5 k, 1%, 0.1 W, 0603", Manufacturer=Vishay-Dale, Power_W=0.1, Supplier Part Number 1=541-25.5KHCT-ND, TempCo="100 ppm/C", Tolerance_%=1, Value1=1%, Value2=0.1W, Value_Code=25k5, ValueDisplayed=25.5k
R112 R113: "RES, 0, 5%, 0.125 W, 0805", Manufacturer=Panasonic, Power_W=0.125, Supplier Part Number 1=P0.0ACT-ND, TempCo="600 ppm/C", Tolerance_%=5, Value1=5%, Value2=0.125W, Value_Code=0000, ValueDisplayed=0
S1: "Switch, SPST-NO,  Off-Mom, 0.05A, 12VDC, SMD", CurrentRating_mA=50, Manufacturer="C&K Components", Supplier Part Number 1=CKN10505CT-ND
TP1 TP2 TP5 TP6 TP11 TP15 TP17 TP18 TP19 TP20 TP22 TP23 TP29 TP31 TP34 TP36 TP40 TP43 TP44 TP49: "Test Point, Miniature, Red, TH", Color=Red, Manufacturer=Keystone, Supplier Part Number 1=36-5000-ND
TP3: library part PogoPad, "Pad for Pogo Pin Connector"
TP4 TP7 TP8 TP9 TP10 TP12 TP13 TP14 TP16 TP28 TP30 TP33 TP38 TP42 TP45 TP46 TP47 TP48: "Test Point, Miniature, White, TH", Color=White, Manufacturer=Keystone, Supplier Part Number 1=36-5002-ND
TP21 TP26 TP32 TP35 TP37 TP39 TP41: "Test Point, Miniature, Black, TH", Color=Black, Manufacturer=Keystone, Supplier Part Number 1=36-5001-ND
TP24: "Test Point, Miniature, Red, TH", Manufacturer=Keystone, Supplier Part Number 1=5000K-ND
U1: "Wide Input 65V, 1.5A Synchronous Step-Down DC-DC Converter, DNT0012B", Alternate Manufacturer="Texas Instruments", Alternate PartNumber=LM5160DNTT, Supplier Part Number 1=296-46122-1-ND
U2: "Positive and Negative Output DC-DC Converter, RGE0024B", Alternate Manufacturer="Texas Instruments", Alternate PartNumber=TPS65130RGET, Supplier Part Number 1=296-17080-1-ND
U3: library part LM27762DSSR, "Low-Noise Regulated Switched-Capacitor Voltage Inverter and Positive LDO, DSS0012B", Alternate Manufacturer="Texas Instruments", Supplier Part Number 1=296-44944-1-ND
U4: "Wide-VIN (±33 V), 150-mA, Spilt-Rail Output, Positive and Negative LDO Voltage Regulator with Startup Tracking, DSC0010J", Alternate Manufacturer="Texas Instruments", Supplier Part Number 1=296-47504-1-ND
U5: "2.5 V, 50 ppm / degC, 50 uA Series (Bandgap) Voltage Reference, -40 to 125 degC, 3-pin SOT-23 (DBZ), Green (RoHS & no Sb/Br)", Alternate Manufacturer="Texas Instruments", Alternate PartNumber=Equivalent, Rating=Catalog, Supplier Part Number 1=296-26322-1-ND, Temp Coeff(Max)(ppm/ degree C)=50, Temp Coeff(Typ)(ppm/ degree C)=20
U6: library part CMP-0040811-1, "Precision, Low Noise, Low Quiescent Current Operational Amplifier, 2 to 5.5 V, -40 to 125 degC, 8-pin SOIC (D8), Green (RoHS & no Sb/Br)", Manufacturer="Texas Instruments", Supplier Part Number 1=296-22630-1-ND, Total Supply Voltage(Max)(+5V is 5, +/-5V is 10)=5.5, Total Supply Voltage(Min)(+5V is 5, +/-5V is 10)=2
U7: "Low Noise, Very Low Drift, Precision Voltage Reference, -40 to 125 degC, 8-pin MSOP(DGK), Green (RoHS & no Sb/Br)", Alternate Manufacturer="Texas Instruments", Alternate PartNumber=Equivalent, Rating=Military, Supplier Part Number 1=296-24498-1-ND, Temp Coeff(Max)(ppm/ degree C)=3
U8 U28: "Precision Micropower Shunt Voltage Reference, 3-pin SOT-23, Pb-Free", Manufacturer="Texas Instruments", PackageTopMarking=R2A*XTT, PowerWise=N, Supplier Part Number 1=LM4040AIM3-2.5/NOPBCT-ND
U9: library part CMP-0076506-2, "1.5V-Capable, 10 uA Analog Output Temperature Sensor in SC70 and TO-92, LP0003A (TO-92-3)", Alternate Manufacturer="Texas Instruments", Supplier Part Number 1=LMT84LPM-ND
U10: "Single Output LDO, 150 mA, Fixed 3.3 V Output, 2.5 to 24 V Input, with Ultra-Low IQ, 5-pin SOT-23 (DBV), -40 to 125 degC, Green (RoHS & no Sb/Br)", Alternate Manufacturer="Texas Instruments", Alternate PartNumber=Equivalent, Supplier Part Number 1=296-39285-1-ND
U11 U16 U19 U22 U46 U47: library part CMP-0013424-7, "33-V Precision Surge Protection Clamp, DRV0006A (WSON-6)", Alternate Manufacturer="Texas Instruments", Alternate PartNumber=TVS3300DRVT, Supplier Part Number 1=296-47565-1-ND
U12 U14 U15 U41: library part CMP-0077837-1, "5-V Precision Surge Protection Clamp, DRV0006A (WSON-6)", Alternate Manufacturer="Texas Instruments", Supplier Part Number 1=296-48382-1-ND
U17: "7V - 57V, 800mA Industrial eFuse with Integrated Reverse Polarity Protection, DRC0010J (VSON-10)", Alternate Manufacturer="Texas Instruments", Alternate PartNumber=TPS26625DRCR
U18: "AUTOSWITCHING POWER MUX, DRB0008B (VSON-8)", Alternate Manufacturer="Texas Instruments", Alternate PartNumber=TPS2115ADRBT, Supplier Part Number 1=296-23394-1-ND
U20: "SIMPLE SWITCHER 3.5V to 60V 2.5A Synchronous Step-Down Voltage Regulator, RNP0030B (WQFN-30)", Alternate Manufacturer="Texas Instruments", Alternate PartNumber=LM76002RNPT, Supplier Part Number 1=LM76002RNPR-ND
U21: library part CMP-0080899-1, "SIMPLE SWITCHER (R) 6V to 42V, 2A Power Module in Leaded SMT-TO Package, NDW0007A (TO-PMOD-7)", Alternate Manufacturer="Texas Instruments", Alternate PartNumber=LMZ14202TZX-ADJ/NOPB, Supplier Part Number 1=LMZ14202TZ-ADJ/NOPBCT-ND
U23: library part CMP-0076397-2, "Zero Iq Reverse Polarity Protection Smart Diode Controller, DGK0008A (VSSOP-8)", Alternate Manufacturer="Texas Instruments", Supplier Part Number 1=296-43067-1-ND
U24: library part CMP-0067322-1, "Overvoltage/Undervoltage Protection IC in SOT-23-5, DBV0005A (SOT-23-5)", Alternate Manufacturer="Texas Instruments", Alternate PartNumber=TPS2400DBVT, Supplier Part Number 1=296-17744-1-ND
U25: "LDO with 4.7 to 15 V Input and 3.3 V Output, -40 to 125 degC, 8-Pin SON (DRJ), Green (RoHS & no Sb/Br)", Alternate Manufacturer="Texas Instruments", Alternate PartNumber=Equivalent, Supplier Part Number 1=296-32364-1-ND
U26: library part CMP-0076880-1, "Automotive-Grade, Voltage Output, Low- or High-Side Measurement, Bidirectional, Zero-Drift Series, Current-Shunt Monitor, DCK0006A (SOT-SC70-6)", Alternate Manufacturer="Texas Instruments", Supplier Part Number 1=296-44264-1-ND
U27: library part CMP-0036669-1, "Single Output Fast Transient Response LDO, 1 A, Adjustable 1.2 to 20 V Output, 2.2 to 20 V Input, 6-pin SOT-223 (DCQ), -40 to 125 degC, Green (RoHS & no Sb/Br)", Manufacturer="Texas Instruments", Supplier Part Number 1=296-39489-1-ND
U29: library part CMP-0074247-1, "Wide VIN Voltage Detector, DSE0006A (WSON-6)", Alternate Manufacturer="Texas Instruments", Alternate PartNumber=TPS3710DSET, Supplier Part Number 1=296-48736-2-ND
U30: library part CMP-0074269-1, "150-nA, Ultralow Power, Supply Voltage Monitor, DBZ0003A (SOT-23-3)", Alternate Manufacturer="Texas Instruments", Alternate PartNumber=TPS3839E16DBZT, Supplier Part Number 1=296-40757-1-ND
U31: library part CMP-0067355-1, "Voltage Monitor With Watchdog Timer, DBV0005A (SOT-23-5)", Alternate Manufacturer="Texas Instruments", Alternate PartNumber=TPS3828-33DBVT, Supplier Part Number 1=296-32484-2-ND
U32 U35: library part CMP-0065262-5, "36-V 0.5-A Step-Down DC-DC Nano Module, SIL0010A (uSIP-10)", Alternate Manufacturer="Texas Instruments", Alternate PartNumber=LMZM23600SILT
U34 U36 U38 U39 U48 U49: library part CMP-0077836-1, "14-V Precision Surge Protection Clamp, DRV0006A (WSON-6)", Alternate Manufacturer="Texas Instruments", Supplier Part Number 1=TVS1400DRVR-ND
U40: library part CMP-0077833-1, "27-V Precision Surge Protection Clamp, DRV0006A (WSON-6)", Alternate Manufacturer="Texas Instruments"
U42: library part CMP-0051912-2, "Dual Buffer Gate, DRL0006A, LARGE T&R", Alternate Manufacturer="Texas Instruments", F @ Nom Voltage(Max)(Mhz)=150, Generic Part Number=SN74LVC2G34, ICC @ Nom Voltage(Max)(mA)=0.01, Operating Temperature Range(C)="-40 to 125,-40 to 85", Rating=Catalog, Supplier Part Number 1=296-18020-1-ND, tpd @ Nom Voltage(Max)(ns)=8.6,4.4,4.1,3.2, Voltage(Nom)(V)=1.8,2.5,3.3,5
U43: library part CMP-0077265-1, "5.5-V, 2-A, 80 mohm Low Leakage Load Switch with RCB and Programmable Rise Time, DBV0006A (SOT-23-6)", Alternate Manufacturer="Texas Instruments", Alternate PartNumber=TPS22917DBVT, Supplier Part Number 1=TPS22917DBVR-ND
U44: library part CMP-0065098-3, "4V to 36 V 0.6 A Synchronous Step-Down Converter, DBV0006A (SOT-23-6)", Alternate Manufacturer="Texas Instruments", Alternate PartNumber=TPS560430XFDBVT
U45: library part CMP-0013051-2, "1uA IQ, 200 mA, Ultralow IQ Low-Dropout Regulator, DBV0005A (SOT-5)", Alternate Manufacturer="Texas Instruments"
U50: library part CMP-0013250-1, "TMP235DCK, DCK0005A (SOT-5)", Alternate Manufacturer="Texas Instruments"
U51: library part CMP-0083672-1, "2.5V Low-Drift Low-Power Small-Footprint Series Voltage Reference, DBV0006A (SOT-23-6)", Alternate Manufacturer="Texas Instruments", Operating Temperature Range="-40 to 125 C", Rating=Catalog
U52: library part CMP-0084478-1, "Nano Power, Wide VIN Voltage Detector with Programmable Delay, DBV0005A (SOT-23-5)", Alternate Manufacturer="Texas Instruments"
ZZ1: library part AssemblyNoteLabel
ZZ2 ZZ3 ZZ4: library part AssemblyNote

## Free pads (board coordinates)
  oval 200x32 hole 32 slot 200 at 0 deg unplated mask+10: 0(141,2141.42) 0(441,2141.42) 0(741,2141.42) 0(1041,2141.42) 0(1341,2141.42) 0(1641,2141.42) 0(1941,2141.42) 0(2241,2141.42) 0(2541,2141.42) 0(2841,2141.42) 0(3141,2141.42)
  oval 230x32 hole 32 slot 230 at 0 deg unplated mask+10: 0(3457,2141.42)

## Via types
v1: diameter 24, hole 12, Top Layer to Bottom Layer, tented both sides, 201 vias
v2: diameter 32, hole 16, Top Layer to Bottom Layer, tented both sides, 134 vias
v3: diameter 19.68, hole 7.87, Top Layer to Bottom Layer, 78 vias
v4: diameter 20, hole 8, Top Layer to Bottom Layer, tented both sides, 11 vias
v5: diameter 32, hole 20, Top Layer to Bottom Layer, tented both sides, 2 vias
v6: diameter 24, hole 10, Top Layer to Bottom Layer, tented both sides, 2 vias

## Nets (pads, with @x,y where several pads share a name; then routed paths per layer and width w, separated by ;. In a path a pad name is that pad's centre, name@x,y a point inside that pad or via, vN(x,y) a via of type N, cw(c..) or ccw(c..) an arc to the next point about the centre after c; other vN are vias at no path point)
3.3V_1: C86.2 C88.2 D12.2 TP18.1 U25.5 U25.6 U25.7 U25.9
  other v2: 1808,1220 1808,1278
  other v3: 1738.12,1039.13 1688.91,1072.6 1738.12,1072.6 1787.33,1072.6 1738.12,1106.06
3.3V_2: C93.2 C95.2 R82.2 TP19.1 U27.2 | length 432.3
  Top Layer w20: R82.2@2066.54,1312.39 2066.54,1403.54 2093,1430 2284,1430 ; U27.2@2230.54,1147.02 2233.6,1150.08 2233.6,1222.46 C93.2@2259.03,1247.89
3V3_S: C126.1 TP36.1 U45.5
5V_S: C125.1 C129.1 C130.1 C131.2 L8.2 R106.2 TP34.1 U45.1 U45.3 | length 931.7
  Top Layer w25: R106.2@903.57,361.98 906.57,358.98 v1(955.07,358.98) ; C129.1@1483.07,202.91 v1(1483.07,247.98) ; v1(1894.57,198.47) C125.1@1944.07,198.47 ; v1(1981.07,86.98) 2017.67,123.57 U45.3@2028.94,123.57
  Bottom Layer w25: v1(955.07,358.98) 1009.07,358.98 1120.07,247.98 v1(1483.07,247.98) ; v1(1894.57,198.47) 1981.07,111.97 v1(1981.07,86.98)
24V/12V_IN: J14.2 PT2.1
+2.5V: R80.1 R83.1 TP15.1 U28.1 | length 348.6
  Top Layer w20: R80.1@2391.18,569.64 2392.78,568.04 U28.1@2460.38,568.04 ; R83.1@2465.19,633.64 2460.38,628.83 U28.1@2460.38,568.04 ; TP15.1@2657,533 2621.96,568.04 U28.1@2462.34,568.04 U28.1@2460.38,568.04
+3.3V: C46.1 C47.2 C49.2 C53.1 C54.1 C56.2 C59.1 C99.1 C100.1 C135.2 C137.1 C139.1 R46.1 R86.1 R87.1 R94.1 R119.1 TP49.1 U5.1 U6.8 U7.2 U9.1 U10.3 U30.3 U31.5 U50.4 U51.3 U51.4 U52.2 | length 1692.4
  Top Layer w15: U50.4@3499.52,3000.41 3560.94,3000.41 C135.2@3561.61,3001.09 v1(3561.61,2958)
  Top Layer w20: R86.1@2424.25,2863.5 2452,2835.76 U30.3@2523.25,2835.76 ; U30.3@2523.25,2839.69 2617.44,2839.69 C99.1@2622.25,2844.5 2622.25,2744.25 TP49.1@2621,2743 2621,2644.72 v1(2607,2630.72) ; R119.1@2608.06,3065.82 2609.86,3064.02 C139.1@2680.57,3064.02 ; v1@2680.57,3017.18 C139.1@2680.57,3064.02 ; U52.2@2707.36,3135.32 2707.36,3096.93 2680.57,3070.14 C139.1@2680.57,3064.02 ; v1(2753.5,2792.5) C137.1@2806,2792.5 2806.33,2792.17 U51.4@2875.6,2792.17 U51.3@2875.6,2900.44 ; R87.1@2821,3155.7 v1(2821,3202.63) ; v1(2838.57,3238.2) C100.1@2885.5,3238.2 ; v1(2885.5,3285.13) C100.1@2885.5,3238.2 ; U31.5@2885.6,3178.4 U31.5@2885.6,3182.33 2885.6,3238.11 C100.1@2885.5,3238.2 ; v1(2898.05,2965.25) R94.1@2898.05,3012.18 ; v1@3094.3,2270.43 C47.2@3094.3,2315.23 ; U6.8@3094.52,2375.23 3094.52,2315.45 C47.2@3094.3,2315.23 ; v1(3140,2314.72) 3139.49,2315.23 C47.2@3094.3,2315.23 ; v1(3399.5,3124.5) C56.2@3399.5,3167 3464,3167 3480,3183 U9.1@3543,3183 ; v1(3468.35,2912.38) C49.2@3468.35,2863.72 3468.85,2863.22 R46.1@3468.85,2781.22
  other v1: 3094.81,2269.92 2533,2556.72 2570,2556.72 2607,2556.72 2607,2593.72 2680.57,3017
+5V_IN: C58.1 L3.1 R19.2 R112.2 R113.2 TP44.1 U10.2
  other v1: 2612.85,2312.4 2499,2346 2554,2363 2468,2418.72 2468,2459.72 2468,2500.72 1575.88,2733.43 1548.88,2752.43 3010,3427 3010,3459 3010,3493 1279,3658 1279,3699 1197,3740 1238,3740 1279,3740
+12V: R24.2 R25.2 TP29.1 U38.4 U38.5 U38.6 | length 91.8
  Top Layer w15: 2273.94,4064.86 2273.94,4077.74 U38.6@2270.61,4081.06 2273.94,4084.39 2273.94,4103.33 U38.5@2270.61,4106.65 2273.94,4109.98 2273.94,4128.92 U38.4@2270.61,4132.24 2273.94,4135.57 2273.94,4148.44
+14V: C16.1 C17.1 R14.1 R22.2 R26.1 R38.1 TP1.1 | length 933.3
  Top Layer w20: R22.2@2086.73,2974.16 R14.1@2086.73,3050.16 ; R22.2@2086.88,2980.43 2118.73,2948.58 C16.1@2118.73,2914.16
  Top Layer w30: R26.1@2247.4,3467.35 2250.73,3464.02 TP1.1@2250.73,2914.16 ; R38.1@2362.25,3467.35 R38.1@2362.4,3467.5
  Top Layer w40: C17.1@2027.73,2914.16 C17.1@2038.73,2914.16 C16.1@2118.73,2914.16 TP1.1@2250.73,2914.16
+24V_IN: C74.1 J9.2 R64.2 U20.20 U20.21 U20.22 | length 67.1
  Top Layer w10: 1674.34,1693.67 U20.20@1709.58,1693.67 ; 1677.71,1654.3 U20.22@1709.58,1654.3
  other v2: 1520,1649 1520,1692
+24V_IN1: C101.1 C104.1 C105.1 J16.1 TP23.1 U32.3 U32.4 U35.3 U35.4 | length 109.7
  Top Layer w12: 271.11,1662.11 U32.3@271.11,1692
  Top Layer w15: 895.2,1650.21 U35.3@895.2,1693.94 ; U35.4@918.82,1693.94 918.82,1675.49 926.09,1668.22 926.09,1660.86
  other v2: 811,1447 854,1447 897,1447 282,1510 325,1510 368,1510 811.09,1511.86 854.09,1511.86 897.09,1511.86
-12V: R40.2 R41.2 TP31.1 U39.1 U39.2 U39.3 U39.7@2554,4106.72 | length 154.5
  Top Layer w25: v1(3383.53,3594.65) R40.2@3435.03,3594.65 ; v1(3436.36,3541.82) R40.2@3436.36,3593.33 ; R40.2@3437.68,3592.01 v1(3489.18,3592.01)
  other v3: 2554,4085.06 2554,4128.37
-14V: C25.2 C26.2 R21.2 R23.2 R33.1 TP2.1 | length 1475.7
  Top Layer w20: R23.2@2050.73,2529.16 2050.73,2517.16 2087.73,2480.16 R21.2@2087.73,2454.16
  Top Layer w30: R23.2@2050.73,2529.16 2107.73,2586.16 C26.2@2107.73,2687.16 ; TP2.1@2237.73,2687.16 TP2.1@2251.73,2701.16 2324.22,2773.64 2324.22,3205.32 2586.4,3467.5 R33.1@2655.4,3467.5
  Top Layer w40: C25.2@2027.73,2687.16 C25.2@2038.73,2687.16 2107.73,2687.16 C26.2@2118.73,2687.16 TP2.1@2237.73,2687.16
